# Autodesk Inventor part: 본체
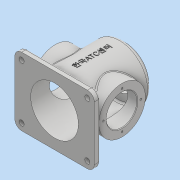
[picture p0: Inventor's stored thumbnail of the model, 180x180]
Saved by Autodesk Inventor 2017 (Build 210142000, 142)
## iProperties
Part Number: 본체
Material: 일반
Document SubType Name: Modeling
Designer: MRC
Density: 1 g/cm^3
Appearance: 기본값
Author: MRC
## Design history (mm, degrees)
sketch "스케치1"
  geometry: C1 r 50 at (0, 0); 1 further point
  constraints: 1 centre point, 1 coincident
  dimensions: "d0" = 100 diameter of C1
extrude "돌출1" new body sketch "스케치1" stored distance "d1" = 120; taper "d2" = 0 deg
sketch "스케치2"
  geometry: L1 (70, -60)-(-70, -60); L2 (-70, -60)-(-70, 60); L3 (-70, 60)-(70, 60); L4 (70, 60)-(70, -60); L5 (70, -60)-(-70, 60); L6 (-70, -60)-(70, 60); C1 r 50 at (0, 0); 1 further point
  constraints: 12 end point, 2 midpoint, 2 parallel, 1 centre point, 1 coincident, 1 horizontal, 1 perpendicular
  dimensions: "d3" = 140 distance of L2.end L3.end; "d4" = 120 distance of L1.end L2.end; "d14" = 100 diameter of C1
sketch "스케치3"
  geometry: C1 r 41 at (0, 0); 1 further point
  constraints: 1 centre point, 1 coincident
  dimensions: "d7" = 82 diameter of C1
extrude "돌출3" join sketch "스케치3" distance "d8" = 5; taper "d9" = 0 deg
node "작업 평면1"
sketch "스케치4"
  geometry: C1 r 41 at (0, 0); 1 further point
  constraints: 1 centre point, 1 coincident
  dimensions: "d11" = 82 diameter of C1
extrude "돌출4" join sketch "스케치4" stored distance "d12" = 5; taper "d13" = 0 deg
extrude "돌출5" join sketch "스케치2" distance "d15" = 10; taper "d16" = 0 deg
sketch "스케치5"
  geometry: 2 further points
  constraints: 1 coincident
hole "구멍1" sketch "스케치5" at (0, 0) diameter "d17" = 54; stored, may be unused: countersink angle "d21" = 90 deg, drill point angle "d23" = 118 deg; dims "d18" = 6, "d19" = 84, "d20" = 112, "d22" = 8
sketch "스케치6"
  geometry: C1 r 27 at (0, 0); 1 further point
  constraints: 1 centre point, 1 coincident
  dimensions: "d24" = 54 diameter of C1
extrude "돌출6" cut sketch "스케치6" stored distance "d25" = 10; taper "d26" = 0 deg
sketch "스케치7"
  geometry: 2 further points
  constraints: 1 vertical alignment
  dimensions: "d27" = 33 distance of point (0, 0) point (0, 33)
hole "구멍2" sketch "스케치7" at (0, 33) diameter "d28" = 3.242; stored, may be unused: countersink angle "d32" = 90 deg, drill point angle "d34" = 118 deg; dims "d29" = 8, "d30" = 84, "d31" = 112, "d33" = 10
chamfer "모따기1" distance "d38" = 1; stored, may be unused: second distance "d39" = 2, angle "d40" = 45 deg
chamfer "모따기2" distance "d41" = 1; stored, may be unused: second distance "d42" = 2, angle "d43" = 45 deg
sketch "스케치8"
  geometry: 2 further points
  constraints: 1 vertical alignment
  dimensions: "d44" = 33 distance of point (0, 0) point (0, 33)
hole "구멍3" sketch "스케치8" at (0, 33) diameter "d45" = 3.242; stored, may be unused: countersink angle "d49" = 90 deg, drill point angle "d51" = 118 deg; dims "d46" = 8, "d47" = 84, "d48" = 112, "d50" = 10
fillet "모깎기1" dims "d55" = 12, "d62" = 6
sketch "스케치9"
  geometry: C1 r 4.5 at (-58, 48); C2 r 4.5 at (58, 48); C3 r 4.5 at (58, -48); C4 r 4.5 at (-58, -48); A1 r 12 centre (-58, 48) between (-58, 60) and (-70, 48) reference; A2 r 12 centre (58, 48) between (70, 48) and (58, 60) reference; A3 r 12 centre (58, -48) between (58, -60) and (70, -48) reference; A4 r 12 centre (-58, -48) between (-70, -48) and (-58, -60) reference; 1 further point
  constraints: 4 centre point, 4 coincident
  dimensions: "d56" = 9 diameter of C1; "d57" = 9 diameter of C2; "d58" = 9 diameter of C3; "d59" = 9 diameter of C4
extrude "돌출7" cut sketch "스케치9" stored distance "d60" = 10; taper "d61" = 0 deg
fillet "모깎기2" dims "d63" = 3
node "작업 평면2"
sketch "스케치10"
  geometry: L1 (-58, -60)-(58, -60) reference; 2 further points
  constraints: 1 vertical alignment, 1 other
  dimensions: "d64" = 66 distance from line of point (0, 6) L1
feature "엠보싱1" sketch "스케치10" dims "d65" = 0.5, "d66" = 0
node "솔리드1"
pattern_circular "원형 패턴1" dims angle "d36" = 360 deg
mirror "미러1"
pattern_circular "원형 패턴2" dims angle "d53" = 360 deg
other parameters: "d10" = 59
